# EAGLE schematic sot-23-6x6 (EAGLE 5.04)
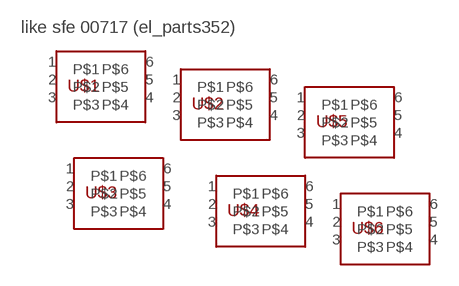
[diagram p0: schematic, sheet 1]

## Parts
U$1  SMD-ADAPTER-SOT-23-6  [SMD-DIP-ADAPTER-SOT-23-6]
U$2  SMD-ADAPTER-SOT-23-6  [SMD-DIP-ADAPTER-SOT-23-6]
U$3  SMD-ADAPTER-SOT-23-6  [SMD-DIP-ADAPTER-SOT-23-6]
U$4  SMD-ADAPTER-SOT-23-6  [SMD-DIP-ADAPTER-SOT-23-6]
U$5  SMD-ADAPTER-SOT-23-6  [SMD-DIP-ADAPTER-SOT-23-6]
U$6  SMD-ADAPTER-SOT-23-6  [SMD-DIP-ADAPTER-SOT-23-6]
Unconnected: U$1.1 U$1.2 U$1.3 U$1.4 U$1.5 U$1.6 U$2.1 U$2.2 U$2.3 U$2.4 U$2.5 U$2.6 U$3.1 U$3.2 U$3.3 U$3.4 U$3.5 U$3.6 U$4.1 U$4.2 U$4.3 U$4.4 U$4.5 U$4.6 U$5.1 U$5.2 U$5.3 U$5.4 U$5.5 U$5.6 U$6.1 U$6.2 U$6.3 U$6.4 U$6.5 U$6.6

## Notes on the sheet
- like sfe 00717 (el_parts352)

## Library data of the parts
U$1-U$6 = trl:SMD-ADAPTER-SOT-23-6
